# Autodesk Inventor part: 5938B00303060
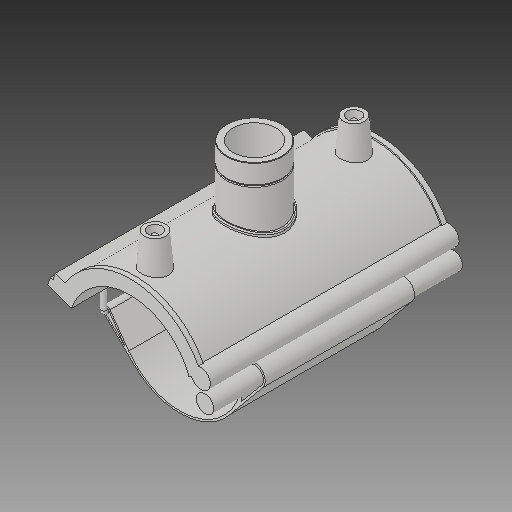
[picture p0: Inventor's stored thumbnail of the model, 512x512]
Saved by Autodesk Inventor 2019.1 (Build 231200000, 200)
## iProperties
Created: 2017-07
Part Number: 5938B00303060
Material: Generic
Description: PLASSON TRANSITION SADDLE 3''IPS x 1"NPT
Document SubType Name: Modeling
Designer: KIM
Density: 1 g/cm^3
Appearance: Default
Author: KIM
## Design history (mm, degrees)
derived "5938B.ipt"
feature "Solid1::5938B.ipt"
tag "TaggingFeature1"
body "Solid1"
other parameters: "d_" = 88.7, "B_" = 136.652, "H_" = 41.91, "L_" = 176.022, "d_t" = 6, "G_" = 30.291, "d148" = 1.3305, "d160" = 1.3305, "d169" = 1.3305, "d192" = 3.548, "d0" = 88.7, "d1" = 106.44, "d2" = 341.63, "d3" = 22.175, "d4" = 176.022, "d5" = 0, "d40" = 55.3488, "d41" = 42.4074, "d43" = 0, "d45" = 0, "d47" = 95.13, "d48" = 39.3783, "d50" = 0, "d78" = 75.22, "d79" = 15, "d80" = 70.4088, "d82" = 5 deg, "d84" = 4, "d85" = 14, "d86" = 0, "d87" = 3, "d88" = 0, "d96" = 108.5688, "d97" = 3.52044, "d98" = 0, "d102" = 0.90873, "d103" = 30.291, "d104" = 25.146, "d105" = 0, "d106" = 24.2328, "d108" = 0, "d109" = -13.97, "d111" = 0.5, "d112" = 0.5, "d113" = 0, "d114" = 0.5, "d117" = 0.30291, "d120" = 140 deg, "d121" = 24.228, "d122" = 20 deg, "d123" = 425.76, "d124" = 63.864, "d126" = 0, "d143" = 91.361, "d145" = 13.64615, "d149" = 1.3305, "d150" = 15.01077, "d153" = 176.022, "d154" = 0, "d156" = 53.22, "d157" = 160 deg, "d159" = 3.548, "d161" = 1.3305, "d162" = 105.6132, "d163" = 0, "d164" = 44.35, "d167" = 8.87, "d168" = 51.92195, "d170" = 1.3305, "d172" = 0, "d173" = 1, "d175" = 44.35, "d176" = 20 deg, "d177" = 6.209, "d178" = 17.74, "d180" = 0, "d183" = 7.096, "d184" = 4.9672, "d185" = 57.20715, "d186" = 57.20715, "d187" = 53.22, "d188" = 5.322, "d189" = 6.209, "d190" = 0, "d191" = 63.864, "d193" = 3.548, "d194" = 1.81835, "d195" = 90 deg, "d197" = 0, "d199" = 0
